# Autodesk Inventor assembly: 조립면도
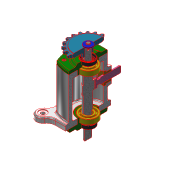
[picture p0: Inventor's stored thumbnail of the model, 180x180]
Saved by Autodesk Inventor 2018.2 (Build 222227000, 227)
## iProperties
Created: 2022-01
Part Number: 조립면도
Document SubType Name: Assembly
Designer: woori
Author: woori
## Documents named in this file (13)
- C:\Users\woori\Desktop\720106V1014\조립면도.iam
- C:\Users\woori\Desktop\720106V1014\본체.ipt
- C:\Users\woori\Desktop\720106V1014\커버.ipt
- C:\Users\woori\Desktop\720106V1014\베어링 6203.ipt
- C:\Users\woori\Desktop\720106V1014\오일 실 17 x 30 x 8.ipt
- C:\Users\woori\Desktop\720106V1014\부시.ipt
- C:\Users\woori\Desktop\720106V1014\볼트 M4 x 12.ipt
- C:\Users\woori\Desktop\720106V1014\편심축.ipt
- C:\Users\woori\Desktop\720106V1014\스프로킷.ipt
- C:\Users\woori\Desktop\720106V1014\키 5 x 5.ipt
- C:\Users\woori\Desktop\720106V1014\와셔 4 x 20.ipt
- C:\Users\woori\Desktop\720106V1014\육각머리볼트 M4.ipt
- C:\Users\woori\Desktop\720106V1014\슬라이더.ipt
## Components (8 placed, 1 different names)
1. M4x0.7x12:1
2. M4x0.7x12:2
3. M4x0.7x12:3
4. M4x0.7x12:4
5. M4x0.7x12:5
6. M4x0.7x12:6
7. M4x0.7x12:7
8. M4x0.7x12:8
